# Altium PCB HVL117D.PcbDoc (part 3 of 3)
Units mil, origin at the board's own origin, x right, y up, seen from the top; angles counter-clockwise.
Board outline 2004.03 x 2004.03 mil, 6 copper layers (Top Layer, InternalPlane1, MidLayer1, InternalPlane2, MidLayer2, Bottom Layer), stack 60.56 mil thick; 218 components, 157 nets, 658 pads, 273 vias.
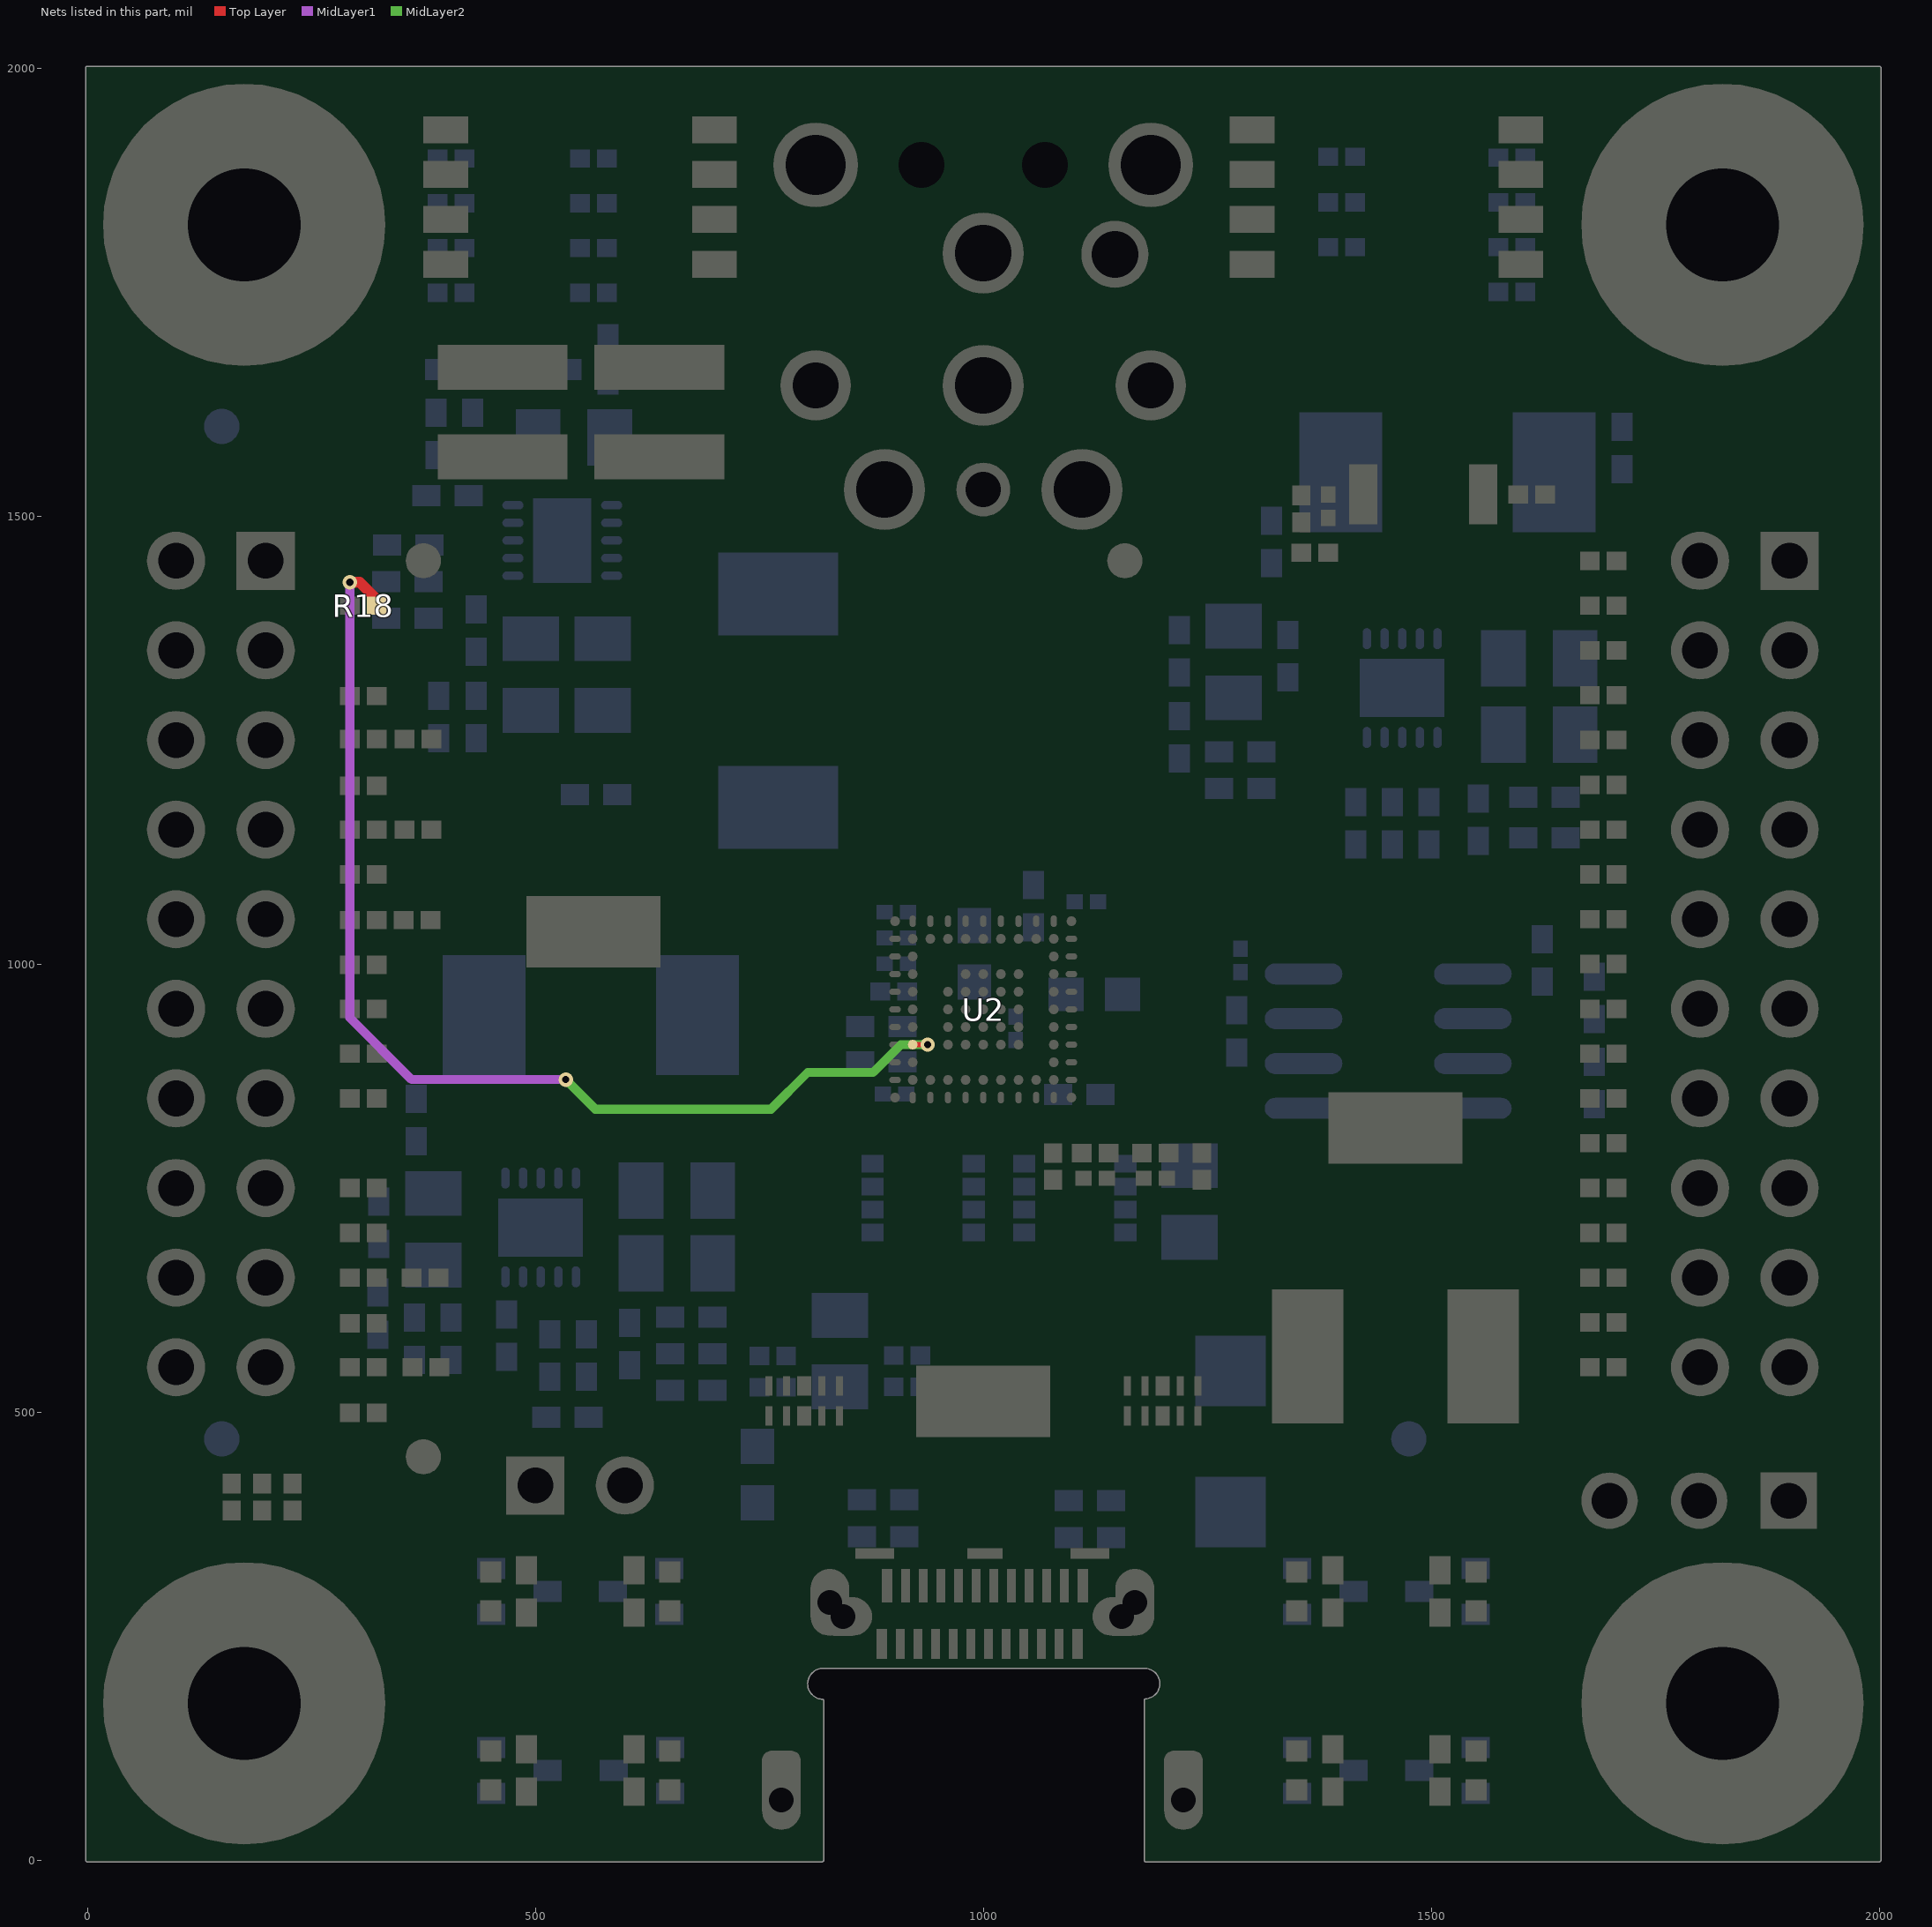
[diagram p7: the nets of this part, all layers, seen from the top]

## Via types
v1: diameter 16, hole 8, Top Layer to Bottom Layer, tented both sides, 166 vias
v2: diameter 16, hole 8.1, Top Layer to Bottom Layer, tented both sides, 54 vias
v3: diameter 20, hole 10, Top Layer to Bottom Layer, tented both sides, 41 vias
v4: diameter 19.68, hole 7.87, Top Layer to Bottom Layer, 12 vias

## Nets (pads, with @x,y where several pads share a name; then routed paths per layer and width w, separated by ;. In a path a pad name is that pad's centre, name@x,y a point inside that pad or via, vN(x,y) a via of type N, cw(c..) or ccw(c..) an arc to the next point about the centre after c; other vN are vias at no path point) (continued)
VOUT_3V3: R18.1 U2.H2 | length 1267.8
  Top Layer w6: U2.H2@921.26,910 v1(938,910) 940.63,910 v1@941,910.37
  Top Layer w10: R18.1@322.96,1400 R18.1@322.96,1407.04
  Top Layer w12: v1(293,1426) 304,1426 R18.1@322.96,1407.04
  MidLayer1 w10: v1(293,1426) 293,940 362,871 v1(534,871)
  MidLayer2 w10: v1(534,871) 567,838 763,838 804,879 877,879 908,910 v1(938,910)
pads on no net: FID1.1 FID2.1 FID3.1 FID4.1 FID5.1 FID6.1 H1.1 H2.1 H3.1 H4.1 J1.A2 J1.A3 J1.A10 J1.A11 J1.B2 J1.B3 J1.B10 J1.B11 J4.10 J4.11 U2.L11

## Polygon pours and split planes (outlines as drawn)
VBUS on Bottom Layer "Mid Layer2 GND Pour" (solid, pour order 11): 890,434 890,450 964,524 1031,591 1150,591 1165,591 1198,624 1198,486 1197,486 1145,434 1120,434
GND on Bottom Layer "Mid Layer2 GND Pour" (solid, remove dead copper, pour order 18): 11,1984 1983,1984 1983,18 1203,18 1202,19 1201,20 1201,147 1201,148 1226,173 1226,214 1226,215 1199,242 802,242 772,212 771,211 771,171 772,171 799,144 799,17 13,17
GND on Top Layer "Mid Layer2 GND Pour" (solid, remove dead copper, pour order 6): 901,1048.37 901.57,1047.8 1098.43,1047.8 1098.43,850.94 901.57,850.94 901.57,1047.8
GND on MidLayer2 "Mid Layer2 GND Pour" (solid, remove dead copper, pour order 20): 16,1983 17,1984 1983,1984 1983,17 1984,16 1983,17 1199,17 1199,148 1223,172 1223,217 1205,235 1205,239 1205,235 1200,240 801,240 799,240 773,214 774,213 774,169 800,143 801,142 801,16 14,16
GND on InternalPlane1 (split plane): 1982.08,18.08 1199.64,17.92 1199.5,163.44 1203.49,166.11 1205.99,168.16 1206.54,168.61 1206.98,169.15 1209.04,171.65 1213.39,178.16 1215.24,181.64 1216.39,185.41 1217.92,193.09 1218.24,196.36 1218.3,197.01 1218.24,197.65 1217.92,200.93 1216.39,208.61 1215.24,212.38 1213.39,215.85 1209.04,222.37 1206.98,224.86 1206.54,225.41 1205.99,225.86 1203.49,227.91 1196.98,232.26 1193.51,234.12 1189.74,235.26 1182.05,236.79 1178.13,237.18 1174.22,236.79 823.78,236.79 819.87,237.18 819.51,237.14 815.95,236.79 808.26,235.26 804.49,234.12 801.02,232.26 794.51,227.91 792.01,225.86 791.46,225.41 791.02,224.86 788.96,222.37 784.61,215.85 782.76,212.38 781.61,208.61 780.08,200.93 779.7,197.01 780.08,193.09 781.61,185.41 782.76,181.64 784.61,178.16 788.96,171.65 791.02,169.15 791.46,168.61 792.01,168.16 794.51,166.11 799.77,162.59 799.77,18.08 18.08,17.92 17.92,1981.92 1981.92,1982.08
GND on InternalPlane2 (split plane): 2001.5,2001.5 2002.1,2000.05 2002.01,2000.05 2001.98,2000.04 2001.96,2000 2002.13,0.01 2001.5,-1.5 2000.05,-2.1 2000.05,-2.02 2000.04,-1.98 2000,-1.96 1181.59,-2.13 1180.07,-1.5 1179.47,-0.05 1179.56,-0.05 1179.6,-0.04 1179.61,0 1179.45,176.41 1179.75,177.14 1179.75,177.15 1179.75,177.16 1179.75,177.18 1179.74,177.18 1179.74,177.2 1185.83,178.41 1185.83,178.42 1185.84,178.42 1192.36,182.77 1192.36,182.78 1192.37,182.79 1196.72,189.3 1196.72,189.31 1196.73,189.32 1198.26,197 1198.26,197.01 1198.26,197.02 1196.73,204.7 1196.72,204.71 1196.72,204.72 1192.37,211.23 1192.36,211.24 1192.36,211.25 1185.84,215.6 1185.83,215.6 1178.14,217.13 1178.13,217.13 1178.12,217.13 1178.1,217.12 1178.09,217.1 1178.08,217.09 1178.08,217.08 1178.08,216.75 819.92,216.75 819.92,217.08 819.92,217.09 819.91,217.1 819.9,217.12 819.88,217.13 819.87,217.13 819.86,217.13 812.17,215.6 812.16,215.6 805.64,211.25 805.64,211.24 805.63,211.23 801.28,204.72 801.28,204.71 801.27,204.7 799.74,197.02 799.74,197.01 799.74,197 801.27,189.32 801.28,189.31 801.28,189.3 805.63,182.79 805.64,182.78 805.64,182.77 812.16,178.42 812.17,178.42 812.17,178.41 819.81,176.89 819.81,10 819.83,9.96 819.87,9.95 822.12,9.95 822.13,0.01 821.5,-1.5 820.05,-2.1 820.05,-2.02 820.04,-1.98 820,-1.96 0.01,-2.13 -1.5,-1.5 -2.1,-0.05 -2.01,-0.05 -1.98,-0.04 -1.96,0 -2.13,1999.99 -1.5,2001.5 -0.05,2002.1 -0.05,2002.01 -0.04,2001.98 0,2001.96 1999.99,2002.13

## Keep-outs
Keep-Out Layer:
  lines w10: -5,3450 cw(c0,3450) 0,3455 ; -5,3450 cw(c0,3450) 0,3455 ; -5,3450 cw(c0,3450) 0,3455 ; -5,3450 cw(c0,3450) 0,3455 ; -5,3450 cw(c0,3450) 0,3455 ; -5,3450 cw(c0,3450) 0,3455 ; 4950,3455 cw(c4950,3450) 4955,3450 ; 4950,3455 cw(c4950,3450) 4955,3450 ; 4950,3455 cw(c4950,3450) 4955,3450 ; 4950,3455 cw(c4950,3450) 4955,3450 ; 4950,3455 cw(c4950,3450) 4955,3450 ; 4950,3455 cw(c4950,3450) 4955,3450
  text ".Layer_Name" at 577,-858.49 h60

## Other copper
Top Layer:
  rectangle net GND: 761,240 891,356
  rectangle net GND: 1106,239 1234,356
  rectangle net GND: 787,269 900,356
  rectangle net HV_SOURCE: 996.01,1059.37 1042,1105.59
  region net NetC6_1: 1112.6,913.17 1112.6,867.37 1152,867.37 1152,913.17
  rectangle net C_SBU_P: 1027.24,319 1034,331
  rectangle net DEBUG_CTL1: 951.6,964.2 961,969.06
  rectangle net GND: 490,1048 640,1096
  rectangle net SYSTEM_3V3: 691,1684 699,1693
  region net GND: 983,347.24 983,362 1014,393 1144,393 1181,356 1181,338 1177,334 1175.57,335.43 1088.57,335.43 1081,348 1075,359 1042,359 1022,335.43 1021.43,336 982.95,336
  region net GND: 1200,143 1200,30 1208,22 1254,22 1275,43 1275,330 1249,356 1216,356 1202,342 1202,239 1229,212 1229,171 1228,171
  region net GND: 802,240 801,240 773,212 773,170 799,144 799,32 790,23 754,23 733,44 733,328 761,356 792,356
  region net HV_SOURCE: 1015.2,1022.97 1024.2,1022.97 1024.2,1029.97 1037.2,1042.97 1042.2,1042.97 1042.2,1061.97 996.2,1061.97 996.2,1042.97 1002.2,1042.97 1015.2,1029.97
  region net NetC6_1: 1073.6,894.17 1073.6,885.17 1080.6,885.17 1093.6,872.17 1093.6,867.17 1112.6,867.17 1112.6,913.17 1093.6,913.17 1093.6,907.17 1080.6,894.17
  region net SYSTEM_5V: 1094,985.37 1125,985.37 1140,1000.37 1140,1050.37 1133,1057.37 1094,1057.37
  pour cut-out: 974,924 975,925 975,969 974,970 971,970 971,924
  pour cut-out: 982,974 1048,974 1048,979 982,979
  pour cut-out: 1064,968 1064,931 1068,931 1068,968
  region net GND: 950,898 953,898 957,902 957,911 960,914 967,914 976,923 976,970 974,970 974,924 966,916 959,916 955,912 955,903
  region net GND: 980,973 1036,973 1036,974 980,974
  region net GND: 956,882 977,882 987,892 987,916 992,921 1027,921 1032,916 1032,887 1037,882 1048,882 1048,913 1033,928 992,928 981,917 981,894 975,888 956,888
  region net GND: 690.6,819.2 704.4,833 693,833 683.1,823.1 683.1,822.1
  text ".Layer_Name" at 577,-858.49 h60
MidLayer2:
  region net HV_SOURCE: 997,1109 1011,1123 1050,1123 1050,1075 1039,1064 1038,1065 997,1065
  pour cut-out: 679,377 828,377 828,389 712,505 712,723 737,748 737,766 735,768 711,768 685,742 685,390
  pour cut-out: 755,601 974,820 974,915 953,915 947,909 947,901 910,901 875,866 860,866 780,786 780,733.37 777.37,733.37 738,694 738,602
  pour cut-out: 1129,1167 1129,1090 1181,1038 1181,749.7 1133.3,702 1174,702 1206,734 1206,1131 1171,1166
  pour cut-out: 365,1193 442,1193 442,1187 384,1129 384,1095 334,1095 332,1093 331,1094 331,1139 332,1139 369.29,1176.29 369.29,1185.51
  pour cut-out: 442,548 442,509 380,571 380,822.91 393.09,836 401,836 401,834 418,817 418,605 430,593 430,558 443,545 443,511
  pour cut-out: 923,1093 923,1016 932,1007 986,1007 1030,1051 1028,1053 1028,1059 999,1059 993,1065 993,1114 1007,1128 1007,1376 992.63,1376 987.33,1370.71 986,1372.04 986,1375 923,1312 924,1311 924,1020
  pour cut-out: 1362,463 1362,417 1363,416 1809,416 1809,455 1801,463
  pour cut-out: 989,977 991,979 1112,979 1112,1055.89 1120,1063.89 1120,1078 1101,1097 994,990 989,990
Bottom Layer:
  rectangle net NetC6_1: 1109,842 1166,914
  rectangle net GND: 497,1337 598,1477
  rectangle net GND: 422,1380 518,1415
  rectangle net GND: 498,1507 549,1632
  rectangle net GND: 377,1591 524,1632
  rectangle net VBUS: 890,395 1120,434
  rectangle net VBUS: 1198,486 1262,719
  rectangle net NetQ1_5: 910,683 1124,795
  rectangle net NetC1_1: 683,443 767,503
  rectangle net NetC1_1: 662,442 758.5,451.5
  rectangle net GND: 452.3,671.1 548,738.5
  rectangle net GND: 548,671.1 655.3,739.4
  rectangle net GND: 499.7,739.4 655.3,778.9
  rectangle net GND: 589,634.8 656,773.8
  rectangle net GND: 500,722.6 583.1,747.2
  rectangle net SYSTEM_3V3: 671.7,633.4 729.4,1009.6
  rectangle net GND: 1246,1271 1617,1335
  rectangle net GND: 1463,1314 1585,1375
  rectangle net GND: 1534.53,1224 1619,1374.93
  rectangle net "EXTERNAL POWER": 1207.3,1351.5 1433.3,1380.4
  rectangle net GND: 1245.5,1297.6 1372.1,1340.3
  rectangle net SYSTEM_5V: 1632.3,1222.9 1687.3,1616
  rectangle net "EXTERNAL POWER": 574,1507 871,1581
  rectangle net VBUS: 1209,486 1316,531
  rectangle net SYSTEM_5V: 1668,1584 1726,1616
  rectangle net SYSTEM_5V: 1632.3,1085 1687,1222.9
  region net HV_SOURCE: 1008.7,1044.37 1028.7,1064.37 1059,1064.37 1068,1073.37 1068,1105.37 971,1105.37 971,1022.37 1008.7,1022.37
  region net SYSTEM_5V: 1108,1056.37 1108,996.37 1136,968.37 1136,949.67 1174.7,949.67 1175,949.37 1182,956.37 1182,1049.37 1152,1079.37 1119,1079.37 1119,1062.26 1113.11,1056.37
  region net VBUS: 890,414 890,345.05 917.05,318 963,318 963,354 957,360 937,360 933,364 933,414 926,421 894,421
  region net VBUS: 1046,360 1046,318 1098,318 1120,340 1120,415 1114,421 1079,421 1073,415 1073,368 1069,364 1051,364
  region net VBUS: 1120,415 1120,420 1137,437 1134,440 1115,440 1115,423.65 1114,422.65
  region net VBUS: 1315,564 1315,643 1262,696 1262,564
  region net NetC6_1: 1109,823 1146,786 1146,716 1174,716 1188,730 1241,730 1263,752 1263,853 1195,914 1109,914
  region net NetC1_1: 742,489 769,516 769,539 792,539 810,557 874,557 874,495 862,483 807,483 767,443 750,460 728,460
  region net NetQ1_1: 892,686 874,668 874,582 807,582 807,722 847,762 892,762
  region net GND: 458,738 452,738 387,673 354,673 354,589 419,589 419,635.34 460.13,676.47
  region net GND: 563.4,671.1 563.4,671 591.9,642.5 591.9,687.6 569.1,687.6 560.3,696.4
  region net NetC20_2: 397.6,876.2 482.3,791.5 484.1,791.5 484.1,885.7 476.5,893.3 403.2,893.3
  region net SYSTEM_3V3: 631.7,875.9 684.7,822.9 691,822.9 691,888.1 672.9,906.2 670.2,906.2
  region net "EXTERNAL POWER": 284,825 284,725 293,716 417,716 450,749 472,749 472,773 420,825
  region net NetC42_2: 593,1500 796,1500 838,1458 838,1364 716,1364 587.63,1492.37 585.24,1492.37
  region net HV_SOURCE: 463,1315 748,1315 839,1224 839,1128 703,1128 582,1249 463,1249
  region net GND: 1420.4,1340.4 1368.1,1340.4 1355.8,1328.1 1356.2,1327.7 1422.2,1327.7 1427.2,1332.7
  region net GND: 1454.3,1340.5 1464.3,1350.5 1470.1,1350.5 1470.1,1335.8 1474,1331.9 1472.1,1330 1455.8,1330
  region net "EXTERNAL POWER": 1433.3,1380.4 1433.2,1380.4 1411.4,1402.2 1216.3,1402.2 1207,1392.9 1207,1358.2 1413.7,1358.2 1417.4,1361.9
  region net SYSTEM_5V: 1588,1482 1649.3,1420.7 1649.3,1519 1639.6,1509.3 1597,1509.3
  region net NetC31_2: 1445,1405 1355,1495 1395,1535 1429.91,1535 1447.91,1517
  region net NetC31_2: 1353.6,1482 1448.1,1387.5 1448.1,1446.4 1392,1502.5 1376.8,1502.5
  region net "EXTERNAL POWER": 1250,1461 1311,1400 1247,1400 1247,1424 1228,1443
  region net "EXTERNAL POWER": 558,1556 585,1529 585,1575 583,1577 580,1574 560,1574
  region net "EXTERNAL POWER": 608,1619 634,1619 668,1585 599,1585 595,1589
  region net GND: 607,1378 607,1413 592,1428 574,1410 574,1355
  region net GND: 562.5,1519.7 562.5,1534.2 544.8,1551.9 541.1,1548.2 541.1,1517 547,1517 553,1511
  region net GND: 478.1,1556.3 499.6,1534.8 513.2,1534.8 513.2,1559.4 505.4,1567.2 489.2,1567.2
  region net GND: 449.1,1590.9 449.2,1590.9 493.6,1546.5 495.9,1548.8 495.9,1605.4 452.2,1605.4 452.1,1605.3
  region net HV_SOURCE: 839,1224 1040,1224 1052,1212 1052,1121.37 1068,1105.37 1060.63,1098 954,1098 924,1128 816,1128 816,1188 807,1197
  region net HV_SOURCE: 954,1098 986,1066 986,1142 980,1148 947,1148
  pour cut-out: 1547,1993 1760,1993 1762,1991 1762,1976 1759,1976 1683,1900 1683,1851 1633,1851 1559,1925 1559,1961 1555,1961 1550,1966
  pour cut-out: 1301,1516 1348,1516 1348,1626 1326,1626 1326,1566 1301,1541
  pour cut-out: 908,1332 908,1225 1071,1225 1071,1320 1055,1336 987,1336
  text ".Layer_Name" at 577,-858.49 h60
InternalPlane1 (plane layer: these items are gaps in the copper):
  region: 433,906 451,906 451,942 433,942
  region: 986,262 987,263 1029,263 1029,276 1020,285 995,285 986,276
InternalPlane2 (plane layer: these items are gaps in the copper):
  region: 986,262 986,276 992,282 1023,282 1030,275 1030,263.02
  region: 433,906 451,906 451,942 433,942

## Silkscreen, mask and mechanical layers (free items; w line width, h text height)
Top Overlay:
  drawing of 1037 lines, arcs and shapes, not listed
  text "+" at 1140,1951 h50
  text "GND" at 949,1950 h50
  text "TPS65982EVM" at 50,1619 h50
  text "HVL117" at 137,1591 h30
  text "SVN: REV D" at 137.2,1565 h30
  text "19V-20V" at 767,1519 h50 r90
  text "RESET" at 1421,1396 h50
  text "TPS65982 BoosterPack" at 777,1214 h75
  text "USB Type-C & PD" at 777,1152 h65
  text "GND" at 586,941 h40
  text "VBUS" at 1411,885 h40
  text "CC2" at 1329,661 h40
  text "CC1" at 1527,660 h40
  text "PP_EXT" at 477,516 h40
  text "ENABLE" at 478,478 h40
  text "GND" at 961,416 h40
  text "5V" at 1343,357 h60
  text "HV" at 1492,357 h60
  text "A" at 383,215 h60
  text "B" at 689,215 h60
  text "PVDR" at 1306,162 h60
  text "CONS" at 1462,162 h60
  text "CC1" at 425,161 h60
  text "CC2" at 585,160 h60
  text ".Layer_Name" at 577,-858.49 h60
Bottom Overlay:
  rectangle: 1442,594 1742,694
  text ".PRJ_Number" at 1736,719 h50
  text ".Layer_Name" at 577,-858.49 h60
Top Paste:
  text ".Layer_Name" at 577,-858.49 h60
Bottom Paste:
  text ".Layer_Name" at 577,-858.49 h60
Top Solder:
  text ".Layer_Name" at 577,-858.49 h60
  text ".Layer_Name" at 577,-858.49 h60
Bottom Solder:
  text ".Layer_Name" at 577,-858.49 h60
Drill Guide:
  text ".Layer_Name" at 577,-858.49 h60
M1 Board Outline:
  lines w4: 818.96,177.51 cw(c821.31,196.68) 821.31,216 1180,216 cw(c1180,196.89) 1181.59,177.86 ; 820,177.51 820,0 0,0 0,2000 2000,2000 2000,0 1181.57,0 1181.57,176.43
  text ".Layer_Name" at 577,-858.49 h60
M2 Board Dimensions:
  rectangle: 125,-410.5 500,-285.5
  rectangle: 0,-285.5 125,-160.5
  lines w7: 0,-285.5 1000,-285.5 ; 125,-410.5 125,-160.5 ; 250,-410.5 250,-160.5 ; 500,-410.5 500,-160.5 ; 750,-410.5 750,-160.5 ; 0,-410.5 0,-160.5 1000,-160.5 1000,-410.5 0,-410.5
  text ".Layer_Name" at 577,-858.49 h60
M3 3D STEP Top:
  text ".Layer_Name" at 577,-858.49 h60
M4 3D STEP Bottom:
  text ".Layer_Name" at 577,-858.49 h60
M5 Assembly Top:
  lines w10: -292,-930.17 6308,-930.17 ; -292,-726.83 6310,-726.83 ; -292,-523.5 -292,-1133.5 3713,-1133.5 6310,-1133.5 6310,-523.5 -291.5,-523.5 -291.5,-1133.5 1284,-1133.5 ; 2173,-1133.5 2173,-523.5 ; 3440,-726.83 3440,-523.5 ; 4280,-726.83 4280,-523.5 ; 4902,-1140 4902,-937.17
  text "COMPONENTS MARKED 'DNP' SHOULD NOT BE POPULATED." at 1153.5,-318.5 h60
  text "ASSEMBLY VARIANT:" at 1153,-434 h60
  text ".VariantName" at 2189,-434 h60
  text "PCB VIEWED FROM TOP SIDE" at -228.5,-655.67 h60
  text "BOARD #:" at 2248,-655.67 h60
  text ".PRJ_Number" at 2793.5,-655.67 h60
  text "REV:" at 3638,-655.67 h60
  text ".PCB_Rev" at 3929.5,-655.67 h60
  text "SVN REV:" at 4476,-655.67 h60
  text ".VersionControl_RevNumber" at 4982,-655.67 h60
  text "IGNORE ->" at -228.5,-858.49 h60
  text "PLOT NAME =" at -228.5,-1064.34 h60
  text ".plot_File_Name" at 577,-1064.34 h60
  text "GENERATED    :" at 2250,-1064.34 h60
  text ".Print_Date" at 3119.5,-1064.34 h60
  text ".Print_Time" at 3848.5,-1064.34 h60
  text "TEXAS INSTRUMENTS" at 5113,-1064.34 h60
M6 Assembly Bottom:
  lines w10: -292.5,-727.33 6309.5,-727.33 ; -290.5,-930.67 6309.5,-930.67 ; 1115.5,-1140.5 1115.5,-937.67 ; 1737.5,-727.33 1737.5,-524 ; 2577.5,-727.33 2577.5,-524 ; 3844.5,-1134 3844.5,-524 ; 4733.5,-1134 6309,-1134 6309,-524 -292.5,-524 -292.5,-1134 2304.5,-1134 6309.5,-1134 6309.5,-524
  text "COMPONENTS MARKED 'DNP' SHOULD NOT BE POPULATED." at 6102,-318 h60
  text ".VariantName" at 5058,-434 h60
  text "ASSEMBLY VARIANT:" at 6097,-434 h60
  text ".VersionControl_RevNumber" at 1035.5,-656.17 h60
  text "SVN REV:" at 1541.5,-656.17 h60
  text ".PCB_Rev" at 2088,-656.17 h60
  text "REV:" at 2379.5,-656.17 h60
  text ".PRJ_Number" at 3224,-656.17 h60
  text "BOARD #:" at 3769.5,-656.17 h60
  text "PCB VIEWED FROM BOTTOM SIDE" at 6246,-656.17 h60
  text "IGNORE ->" at 2547.85,-858.49 h60
  text "TEXAS INSTRUMENTS" at 904.5,-1064.84 h60
  text ".Print_Time" at 2169,-1064.84 h60
  text ".Print_Date" at 2898,-1064.84 h60
  text "GENERATED    :" at 3767.5,-1064.84 h60
  text ".plot_File_Name" at 5440.5,-1064.84 h60
  text "PLOT NAME =" at 6246,-1064.84 h60
M9 Title Sheet:
  drawing of 57 lines, arcs and shapes, not listed
  text "1" at 739.84,8036.5 h70
  text "2" at 3235.5,8036.5 h70
  text "3" at 5724.84,8036.5 h70
  text "4" at 8231.51,8036.5 h70
  text "5" at 10730.5,8036.5 h70
  text "6" at 13235.5,8036.5 h70
  text "A" at -416.5,6893.5 h70
  text "A" at 14383.5,6893.5 h70
  text "B" at -416.5,4513.5 h70
  text "B" at 14383.5,4513.5 h70
  text "C" at -416.5,2138.5 h70
  text "C" at 14383.5,2138.5 h70
  text "PROJECT TITLE:" at 11343.5,277.5 h45
  text ".PRJ_Title" at 11393.5,144.17 h70
  text "DESIGNED FOR:" at 11343.5,-23.5 h45
  text ".PRJ_Customer" at 11393.5,-163.5 h70
  text "D" at -416.5,-231.5 h70
  text "D" at 14383.5,-231.5 h70
  text "FILE NAME:" at 11343.5,-323.5 h45
  text ".PCB_File_Name_No_Path" at 11393.5,-443.5 h70
  text "Texas Instruments (TI) and/or its licensors do not warrant the accuracy or completeness of this specification" at 6374,-605.34 h45
  text "ENGINEER:" at 11343.5,-613.5 h45
  text "LAYOUT BY:" at 12848.5,-613.5 h45
  text "or any information contained therein. TI and/or its licensors do not warrant that this design will meet" at 6329.01,-718 h45
  text ".PRJ_Engineer" at 11393.5,-768.49 h70
  text ".PCB_Layout" at 12899,-768.49 h70
  text "the specifications, will be suitable for your application or fit for any particular purpose, or will operate in" at 6329.01,-830.67 h45
  text ".Layer_Name" at 577,-858.49 h60
  text "ALTIUM DESIGNER VERSION:" at 12848.5,-923.5 h45
  text "an implementation. TI and/or its licensors do not warrant that the design is production worthy. You should" at 6329.01,-943.33 h45
  text "completely validate and test your design implementation to confirm the system functionality for your application." at 6374,-1056 h45
  text ".print_Scale" at 11393.5,-1056.83 h70
  text ".Application_BuildNumber" at 12899,-1056.83 h70
  text "1" at 739.84,-1263.5 h70
  text "2" at 3235.5,-1263.5 h70
  text "3" at 5724.84,-1263.5 h70
  text "4" at 8231.51,-1263.5 h70
  text "5" at 10730.5,-1263.5 h70
  text "6" at 13235.5,-1263.5 h70
M10 Fab Notes:
  drawing of 185 lines, arcs and shapes, not listed
  text "DESIGN INFORMATION" at 12381.02,5910 h60
  text "MIN. TRACK WIDTH:" at 11736.46,5730 h60
  text "4" at 12832.7,5730 h60
  text "MIL" at 12987.46,5730 h60
  text "MIN. CLEARANCE:" at 11736.46,5598 h60
  text "0.2" at 12772.7,5598 h60
  text "mm" at 12987.46,5598 h60
  text "MIN. VIA PAD SIZE:" at 11736.46,5466 h60
  text "16" at 12802.71,5466 h60
  text "MIL" at 12987.46,5466 h60
  text "0.05mm (2MIL)" at 12431.46,5324.29 h60
  text "MINIMUM ANNULAR RING" at 11407.23,5320 h60
  text "EXTERNAL" at 13139.46,5320 h60
  text "PER" at 11607.23,5202 h60
  text "IPC-D-275 CLASS 2 LEVEL C" at 11827.23,5202 h60
  text "MIL, HOLES" at 13315.46,5089.71 h60
  text "+/-" at 12923,5089 h60
  text "+/-" at 13777,5089 h60
  text "REGISTRATION TOLERANCES:" at 11407.23,5084 h60
  text "METAL" at 12607,5084 h60
  text "5" at 13183.2,5084 h60
  text "3" at 14016.2,5084 h60
  text "MIL" at 14132.46,5084 h60
  text "MATERIAL:" at 11332.46,4874.54 h60
  text "FR-4 High Tg" at 12318.9,4734.21 h60
  text "FR-408" at 11753.46,4725.64 h60
  text "X" at 12165.46,4725.64 h60
  text "OTHER" at 13241.46,4725.64 h60
  text "62 MIL (1.6mm) +/-10%" at 12073.56,4562.92 h60
  text "THICKNESS:" at 11407.23,4558.64 h60
  text "X" at 11945.4,4558.64 h60
  text "OTHER" at 13358.46,4558.64 h60
  text "TOLERANCE:" at 11407.23,4400.64 h60
  text "X" at 12246.53,4400.64 h60
  text "ANSI IPC-6012 TYPE 3 CLASS 2" at 12433.48,4400.64 h60
  text "IMPEDANCE CONTROL:" at 5720,4310 h120
  text "OTHER +/-" at 12433.46,4244.64 h60
  text "BOW & TWIST:" at 11407.23,4087.64 h60
  text "X" at 12246.53,4087.64 h60
  text "ANSI IPC-6012 TYPE 3 CLASS 2" at 12433.48,4087.64 h60
  text "Layer 1:" at 5726,4069 h120
  text "OTHER +/-" at 12433.46,3929.13 h60
  text "100 OHM differential : 5.0mil trace- 5.5mil spacing" at 5720,3822 h120
  text "DRILLING:" at 11332.46,3790.64 h60
  text "REFERENCE:" at 11407.23,3673.64 h60
  text "X" at 12055.46,3673.64 h60
  text "AS SHOWN" at 12242.46,3673.64 h60
  text "X" at 12956.46,3673.64 h60
  text "NC_DRILL FILES" at 13093.46,3673.64 h60
  text "90 OHM differential : 5.8mil trace- 4.75mil spacing" at 5720,3575 h120
  text "PTH MIN COPPER THICKNESS:" at 11407.23,3515.64 h60
  text "X" at 12757.46,3515.64 h60
  text "1MIL" at 12894.46,3515.64 h60
  text "OTHER" at 13391.46,3515.64 h60
  text "BOARD FINISH:" at 11332.46,3356.64 h60
  text "50 OHM Single-ended : 9.8mil trace" at 5714,3334 h120
  text "SILKSCREEN:" at 11487.68,3238.64 h60
  text "X" at 12436.46,3238.64 h60
  text "TOP" at 12562.46,3238.64 h60
  text "X" at 12946.46,3238.64 h60
  text "BOTTOM" at 13073.46,3238.64 h60
  text "Layer 3:" at 5703,3127 h120
  text "SILKSCREEN COLOR:" at 11487.68,3071.64 h60
  text "X" at 12435.42,3071.64 h60
  text "WHITE" at 12562.46,3071.64 h60
  text "OTHER" at 13073.46,3071.64 h60
  text "SOLDER RESIST COLOR:" at 11487.68,2901.64 h60
  text "100 OHM differential : 4.4mil trace- 6.5mil spacing" at 5686,2869 h120
  text "RED" at 13782,2744 h100
  text "GREEN" at 12182.46,2742.44 h60
  text "BLUE" at 12773.46,2742.44 h60
  text "OTHER" at 13311.46,2742.44 h60
  text "X" at 13166,2740 h60
  text "90 OHM differential : 4.8mil trace- 5.0mil spacing" at 5686,2622 h120
  text "IMMERSION GOLD (ENIG)" at 12393.46,2553.92 h60
  text "ENEPIG" at 13731,2550.64 h60
  text "SURFACE FINISH:" at 11332.46,2549.64 h60
  text "X" at 12206.51,2549.64 h60
  text "IMM. TIN/SILVER OR EQUIV" at 11662,2392.64 h60
  text "OTHER" at 13093.46,2392.64 h60
  text "50 OHM Single-ended : 9.1mil trace" at 5680,2381 h120
  text "ARRAY/PANEL:" at 11332.46,2213.64 h60
  text "CUT AND TRIM PER MECH LAYER 1" at 12393.46,2209.35 h60
  text "N.C. ROUTE" at 12393.46,2057.64 h60
  text "X" at 13072.46,2057.64 h60
  text "V. SCORE" at 13259.46,2057.64 h60
  text "CERTIFICATION:" at 11332.46,1920.64 h60
  text "MATERIALS AND WORKMANSHIP FOR ALL PCBS" at 12057.46,1920.64 h60
  text "TO MEET OR EXCEED THE REQUIREMENTS OF:" at 12057.46,1822.64 h60
  text "VIA FILL FOR ALL 8.1 MIL VIAS USING NON CONDUCTIVE EPOXY." at 5644,1787 h120
  text "X" at 11683.96,1686.13 h60
  text "ANSI IPC-A-600F CLASS ->" at 11822.96,1686.13 h60
  text "X" at 13462.02,1686.13 h60
  text "2" at 13580.96,1686.14 h60
  text "1" at 13265.96,1684.64 h60
  text "3" at 13934.96,1684.64 h60
  text "X" at 11686.02,1526.64 h60
  text "UL 94V-0" at 11822.96,1526.64 h60
  text "X" at 12498.02,1526.64 h60
  text "RoHS" at 12634.96,1526.64 h60
  text "OTHER" at 13279.36,1526.64 h60
  text "PER ORDER" at 13676.42,1526.64 h60
  text "***ATTENTION***" at 5651,1436 h120
  text "ADDITIONAL REQUIREMENTS:" at 11332.46,1385.64 h60
  text "MICROSECTION:" at 11407.23,1270.64 h60
  text "YES" at 12312.96,1270.64 h60
  text "J2 and J3 headers are to be installed on bottom side of board" at 5658,1194 h120
  text "REQUIRED" at 13174.46,1114.49 h60
  text "BARE BOARD ELEC. TEST:" at 11407.23,1111.64 h60
  text "NONE" at 12712.96,1111.64 h60
  text "X" at 13047.46,1111.64 h60
  text "PER ORDER" at 13766.46,1111.64 h60
  text "MANUFACTURER'S UL:" at 11407.23,954.64 h60
  text "RAIL" at 12572.96,950.35 h60
  text "METAL" at 13064.77,950.35 h60
  text "X" at 13440,950 h60
  text "SILK" at 13576.46,950.35 h60
  text ".Layer_Name" at 577,-858.49 h60
M11 Gerber Information:
  lines w10: -292,-930.17 6308,-930.17 ; -292,-726.83 6310,-726.83 ; -292,-523.5 -292,-1133.5 3713,-1133.5 6310,-1133.5 6310,-523.5 -291.5,-523.5 -291.5,-1133.5 1284,-1133.5 ; 2173,-1133.5 2173,-523.5 ; 3440,-726.83 3440,-523.5 ; 4280,-726.83 4280,-523.5 ; 4902,-1140 4902,-937.17
  text "ALL ARTWORK VIEWED FROM TOP SIDE" at -228.5,-655.67 h60
  text "BOARD #:" at 2248,-655.67 h60
  text ".PRJ_Number" at 2793.5,-655.67 h60
  text "REV:" at 3638,-655.67 h60
  text ".PCB_Rev" at 3929.5,-655.67 h60
  text "SVN REV:" at 4476,-655.67 h60
  text ".VersionControl_RevNumber" at 4982,-655.67 h60
  text "LAYER NAME =" at -228.5,-858.49 h60
  text "PLOT NAME =" at -228.5,-1064.34 h60
  text ".plot_File_Name" at 577,-1064.34 h60
  text "GENERATED    :" at 2250,-1064.34 h60
  text ".Print_Date" at 3119.5,-1064.34 h60
  text ".Print_Time" at 3848.5,-1064.34 h60
  text "TEXAS INSTRUMENTS" at 5113,-1064.34 h60
M12 Stackup:
  drawing of 399 lines, arcs and shapes, not listed
  text "Layer" at 9812,7859 h60
  text "Name" at 10221.91,7859 h60
  text "Material" at 11151.66,7859 h60
  text "Thickness" at 12011.42,7859 h60
  text "Constant" at 12661.26,7859 h60
  text "Board Layer Stack" at 13231.12,7859 h60
  text "1" at 9812,7739 h60
  text "Top Overlay" at 10221.91,7739 h60
  text "2" at 9812,7619 h60
  text "Top Solder" at 10221.91,7619 h60
  text "Solder Resist" at 11151.66,7619 h60
  text "0.80mil" at 12011.42,7619 h60
  text "3.3" at 12661.26,7619 h60
  text "3" at 9812,7499 h60
  text "Top Layer" at 10221.91,7499 h60
  text "Copper" at 11151.66,7499 h60
  text "1.40mil" at 12011.42,7499 h60
  text "4" at 9812,7379 h60
  text "Dielectric1" at 10221.91,7379 h60
  text "FR-4" at 11151.66,7379 h60
  text "5.91mil" at 12011.42,7379 h60
  text "4.1" at 12661.26,7379 h60
  text "5" at 9812,7259 h60
  text "InternalPlane1" at 10221.91,7259 h60
  text "Copper" at 11151.66,7259 h60
  text "1.40mil" at 12011.42,7259 h60
  text "6" at 9812,7139 h60
  text "Dielectric4" at 10221.91,7139 h60
  text "FR-4" at 11151.66,7139 h60
  text "7.87mil" at 12011.42,7139 h60
  text "4.1" at 12661.26,7139 h60
  text "7" at 9812,7019 h60
  text "MidLayer1" at 10221.91,7019 h60
  text "Copper" at 11151.66,7019 h60
  text "1.40mil" at 12011.42,7019 h60
  text "8" at 9812,6899 h60
  text "Dielectric2" at 10221.91,6899 h60
  text "FR-4" at 11151.66,6899 h60
  text "24.60mil" at 12011.42,6899 h60
  text "4.1" at 12661.26,6899 h60
  text "9" at 9812,6779 h60
  text "InternalPlane2" at 10221.91,6779 h60
  text "Copper" at 11151.66,6779 h60
  text "1.40mil" at 12011.42,6779 h60
  text "10" at 9812,6659 h60
  text "Dielectric5" at 10221.91,6659 h60
  text "FR-4" at 11151.66,6659 h60
  text "7.87mil" at 12011.42,6659 h60
  text "4.1" at 12661.26,6659 h60
  text "11" at 9812,6539 h60
  text "MidLayer2" at 10221.91,6539 h60
  text "Copper" at 11151.66,6539 h60
  text "1.40mil" at 12011.42,6539 h60
  text "12" at 9812,6419 h60
  text "Dielectric3" at 10221.91,6419 h60
  text "FR-4" at 11151.66,6419 h60
  text "5.91mil" at 12011.42,6419 h60
  text "4.1" at 12661.26,6419 h60
  text "13" at 9812,6299 h60
  text "Bottom Layer" at 10221.91,6299 h60
  text "Copper" at 11151.66,6299 h60
  text "1.40mil" at 12011.42,6299 h60
  text "14" at 9812,6179 h60
  text "Bottom Solder" at 10221.91,6179 h60
  text "Solder Resist" at 11151.66,6179 h60
  text "0.80mil" at 12011.42,6179 h60
  text "3.3" at 12661.26,6179 h60
  text "15" at 9812,6059 h60
  text "Bottom Overlay" at 10221.91,6059 h60
  text ".Layer_Name" at 577,-858.49 h60
M13 Component Bodies Top:
  text ".Layer_Name" at 577,-858.49 h60
M14 Component Bodies Bottom:
  text ".Layer_Name" at 577,-858.49 h60
M15 Courtyards Top:
  text ".Layer_Name" at 577,-858.49 h60
M16 Courtyards Bottom:
  text ".Layer_Name" at 577,-858.49 h60
Drill Drawing:
  circle w1: c3157.97,947.55 r24.89
  circle w1: c3157.97,947.55 r14.93
  circle w1: c3157.97,1992.79 r24.89
  lines w1: 2444.65,-36.17 2457.09,-36.17 2457.09,-48.62 2481.98,-48.62 2481.98,-36.17 2494.42,-36.17 2494.42,-11.29 2481.98,-11.29 2481.98,1.16 2457.09,1.16 2457.09,-11.29 2444.65,-11.29 2444.65,-36.17 ; 2444.65,100.7 2457.09,125.59 2444.65,150.48 2469.53,138.03 2494.42,150.48 2481.98,125.59 2494.42,100.7 2469.53,113.15 2444.65,100.7 ; 2454.6,-31.2 2462.07,-31.2 2462.07,-38.66 2477,-38.66 2477,-31.2 2484.47,-31.2 2484.47,-16.26 2477,-16.26 2477,-8.8 2462.07,-8.8 2462.07,-16.26 2454.6,-16.26 2454.6,-31.2 ; 2454.6,110.66 2462.07,125.59 2454.6,140.52 2469.53,133.06 2484.47,140.52 2477,125.59 2484.47,110.66 2469.53,118.12 2454.6,110.66 ; 3133.08,636.47 3145.52,648.91 3133.08,661.35 3145.52,661.35 3157.97,673.8 3170.41,661.35 3182.85,661.35 3170.41,648.91 3182.85,636.47 3170.41,636.47 3157.97,624.02 3145.52,636.47 3133.08,636.47 ; 3133.08,823.12 3157.97,773.34 3182.85,823.12 3133.08,823.12 ; 3133.08,1071.98 3133.08,1121.76 3182.85,1121.76 3182.85,1071.98 3133.08,1071.98 ; 3133.08,1246.19 3157.97,1271.08 3182.85,1246.19 3157.97,1221.3 3133.08,1246.19 ; 3133.08,1383.07 3133.08,1407.95 3145.52,1407.95 3145.52,1420.4 3170.41,1420.4 3170.41,1407.95 3182.85,1407.95 3182.85,1383.07 3170.41,1383.07 3170.41,1370.62 3145.52,1370.62 3145.52,1383.07 3133.08,1383.07 ; 3133.08,1519.94 3145.52,1544.83 3133.08,1569.72 3157.97,1557.27 3182.85,1569.72 3170.41,1544.83 3182.85,1519.94 3157.97,1532.39 3133.08,1519.94 ; 3133.08,1681.71 3145.52,1694.15 3133.08,1706.59 3145.52,1706.59 3157.97,1719.04 3170.41,1706.59 3182.85,1706.59 3170.41,1694.15 3182.85,1681.71 3170.41,1681.71 3157.97,1669.26 3145.52,1681.71 3133.08,1681.71 ; 3133.08,1868.36 3157.97,1818.58 3182.85,1868.36 3133.08,1868.36 ; 3133.08,2117.22 3133.08,2167 3182.85,2167 3182.85,2117.22 3133.08,2117.22 ; 3133.08,2266.54 3145.52,2266.54 3157.97,2278.99 3170.41,2266.54 3182.85,2266.54 3182.85,2278.99 3170.41,2291.43 3182.85,2303.87 3182.85,2316.32 3170.41,2316.32 3157.97,2303.87 3145.52,2316.32 3133.08,2316.32 3133.08,2303.87 3145.52,2291.43 3133.08,2278.99 3133.08,2266.54 ; 3143.04,641.44 3150.5,648.91 3143.04,656.38 3150.5,656.38 3157.97,663.84 3165.43,656.38 3172.9,656.38 3165.43,648.91 3172.9,641.44 3165.43,641.44 3157.97,633.98 3150.5,641.44 3143.04,641.44 ; 3143.04,813.16 3157.97,783.3 3172.9,813.16 3143.04,813.16 ; 3143.04,1081.94 3143.04,1111.8 3172.9,1111.8 3172.9,1081.94 3143.04,1081.94
  lines w12: 3065.25,280.59 5183.27,280.59 ; 3065.25,2371.07 5183.27,2371.07 ; 3435.61,131.27 3435.61,2520.39 ; 3792.61,131.27 3792.61,2520.39 ; 4454.18,131.27 4454.18,2520.39 ; 4738.32,131.27 4738.32,2520.39 ; 3065.25,131.27 3065.25,2520.39 5183.27,2520.39 5183.27,131.27 3065.25,131.27
  text "Symbol" at 3154.84,2415.86 h72
  text "Quantity" at 3480.41,2415.86 h72
  text "Finished Hole Size" at 3837.41,2415.86 h72
  text "Plated" at 4498.97,2415.86 h72
  text "Hole Type" at 4783.11,2415.86 h72
  text "2" at 3480.41,2266.54 h60
  text "51.18mil (1.300mm)" at 3837.41,2266.54 h60
  text "NPTH" at 4498.97,2266.54 h60
  text "Round" at 4783.11,2266.54 h60
  text "12" at 3480.41,2117.22 h60
  text "7.87mil (0.200mm)" at 3837.41,2117.22 h60
  text "PTH" at 4498.97,2117.22 h60
  text "Round" at 4783.11,2117.22 h60
  text "147" at 3480.41,1967.9 h60
  text "8.00mil (0.203mm)" at 3837.41,1967.9 h60
  text "PTH" at 4498.97,1967.9 h60
  text "Round" at 4783.11,1967.9 h60
  text "54" at 3480.41,1818.58 h60
  text "8.10mil (0.206mm)" at 3837.41,1818.58 h60
  text "PTH" at 4498.97,1818.58 h60
  text "Round" at 4783.11,1818.58 h60
  text "60" at 3480.41,1669.26 h60
  text "10.00mil (0.254mm)" at 3837.41,1669.26 h60
  text "PTH" at 4498.97,1669.26 h60
  text "Round" at 4783.11,1669.26 h60
  text "1" at 3480.41,1519.94 h60
  text "39.37mil (1.000mm)" at 3837.41,1519.94 h60
  text "PTH" at 4498.97,1519.94 h60
  text "Round" at 4783.11,1519.94 h60
  text "45" at 3480.41,1370.62 h60
  text "40.00mil (1.016mm)" at 3837.41,1370.62 h60
  text "PTH" at 4498.97,1370.62 h60
  text "Round" at 4783.11,1370.62 h60
  text "2" at 3480.41,1221.3 h60
  text "51.18mil (1.300mm)" at 3837.41,1221.3 h60
  text "PTH" at 4498.97,1221.3 h60
  text "Round" at 4783.11,1221.3 h60
  text "4" at 3480.41,1071.98 h60
  text "62.99mil (1.600mm)" at 3837.41,1071.98 h60
  text "PTH" at 4498.97,1071.98 h60
  text "Round" at 4783.11,1071.98 h60
  text "2" at 3480.41,922.66 h60
  text "66.93mil (1.700mm)" at 3837.41,922.66 h60
  text "PTH" at 4498.97,922.66 h60
  text "Round" at 4783.11,922.66 h60
  text "4" at 3480.41,773.34 h60
  text "125.98mil (3.200mm)" at 3837.41,773.34 h60
  text "PTH" at 4498.97,773.34 h60
  text "Round" at 4783.11,773.34 h60
  text "2" at 3480.41,624.02 h60
  text "27.56mil (0.700mm)" at 3837.41,624.02 h60
  text "PTH" at 4498.97,624.02 h60
  text "Slot" at 4783.11,624.02 h60
  text "2" at 3480.41,474.7 h60
  text "27.56mil (0.700mm)" at 3837.41,474.7 h60
  text "PTH" at 4498.97,474.7 h60
  text "Slot" at 4783.11,474.7 h60
  text "2" at 3480.41,325.38 h60
  text "27.56mil (0.700mm)" at 3837.41,325.38 h60
  text "PTH" at 4498.97,325.38 h60
  text "Slot" at 4783.11,325.38 h60
  text "339 Total" at 3480.41,176.06 h60
  text ".Layer_Name" at 577,-858.49 h60

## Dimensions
0,-410.5 to 1000,-410.5 on M2 Board Dimensions
0,0 to 0,2000 on M2 Board Dimensions
0,0 to 2000,0 on M2 Board Dimensions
